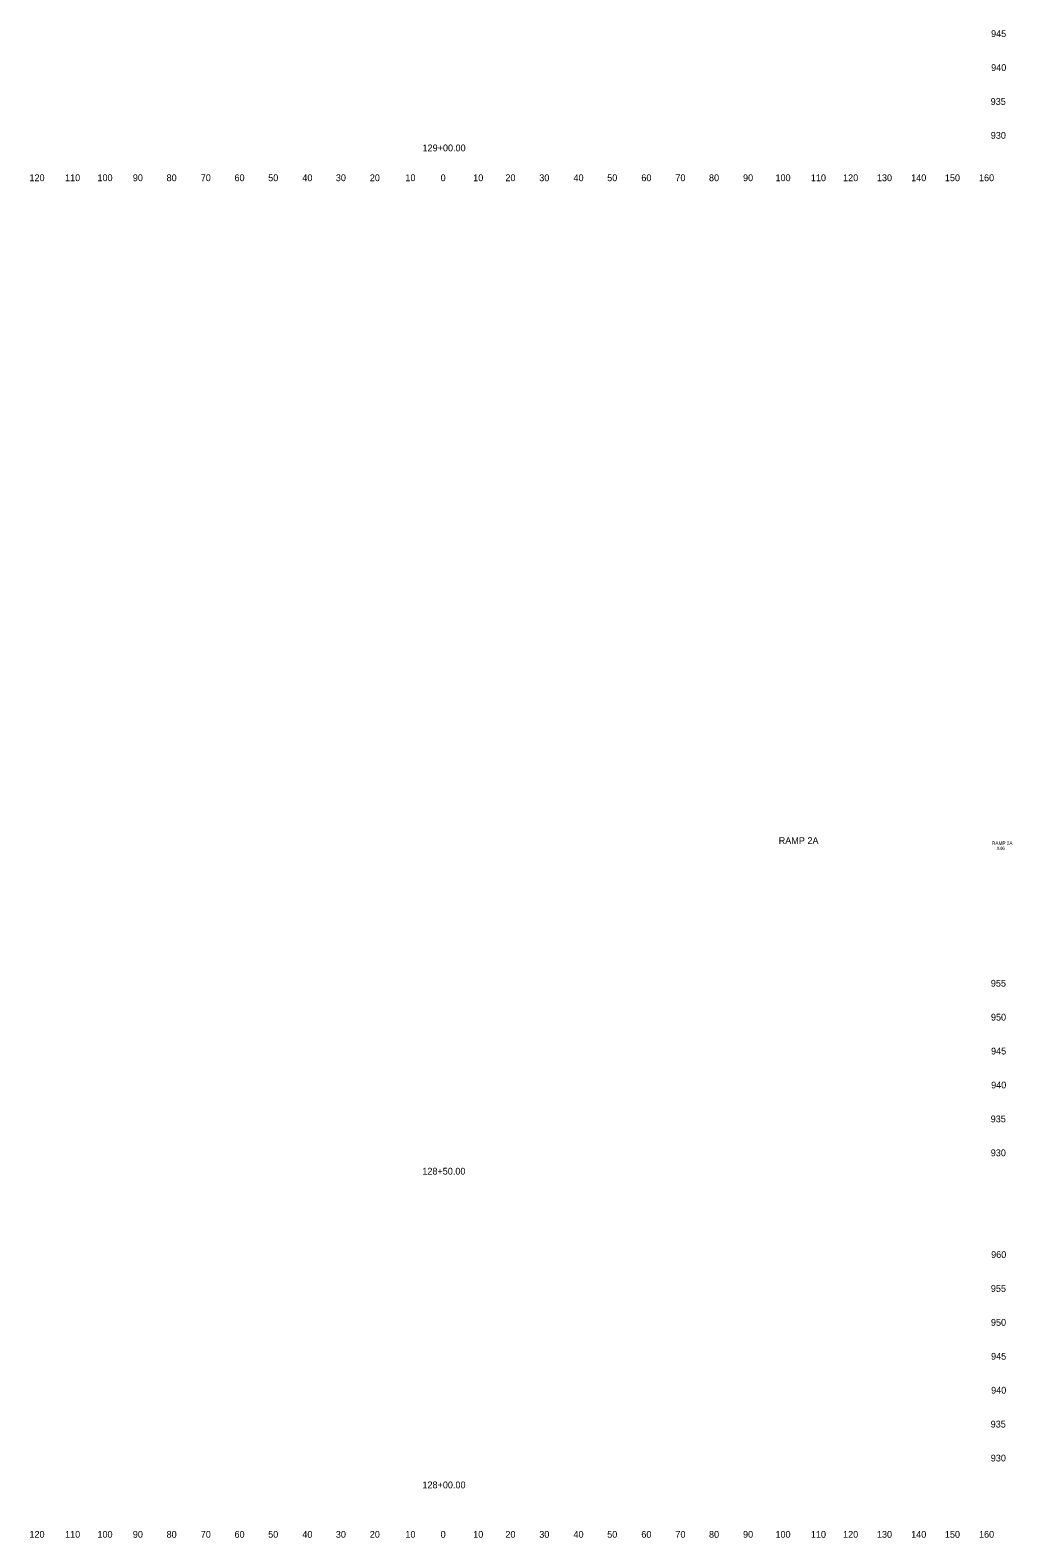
# Model space of a CAD drawing. Extents: x 4994 to 7388, y 4997 to 8804.
# Drawn here: x 7098.2 to 7387.8, y 6997.5 to 7442 of the extents above; entities that cross this region are included whole.
import ezdxf

# ---------------------------------------------------------------- set-up
doc = ezdxf.new("R2010")
doc.units = 0
for name, color, linetype in [('RD_SHT_ID', 7, 'Continuous'), ('RD_XS_TX_Offset', 7, 'Continuous'), ('RD_XS_TX_Station', 7, 'Continuous')]:
    doc.layers.add(name, color=color, linetype=linetype)

msp = doc.modelspace()

# ---------------------------------------------------------------- texts
at = {"layer": 'RD_SHT_ID'}
for s, height, p in [('RAMP 2A', 2, (7319.02, 7202.06)), ('RAMP 2A', 1, (7381.93, 7201.8)), ('X46', 1, (7383.26, 7200.3))]:
    msp.add_text(s, height=height, dxfattribs=at).set_placement(p)
at = {"layer": 'RD_XS_TX_Offset'}
for s, p in [('945', (7381.66, 7440)), ('940', (7381.69, 7430)), ('935', (7381.55, 7420)), ('930', (7381.58, 7410)), ('120', (7098.01, 7397.5)), ('110', (7108.51, 7397.5)), ('100', (7118.07, 7397.5)), ('90', (7128.5, 7397.5)), ('80', (7138.46, 7397.5)), ('70', (7148.54, 7397.5)), ('60', (7158.5, 7397.5)), ('50', (7168.43, 7397.5)), ('40', (7178.5, 7397.5)), ('30', (7188.39, 7397.5)), ('20', (7198.4, 7397.5)), ('10', (7208.91, 7397.5)), ('0', (7219.3, 7397.5)), ('0', (7219.3, 7397.5)), ('10', (7228.91, 7397.5)), ('20', (7238.4, 7397.5)), ('30', (7248.39, 7397.5)), ('40', (7258.5, 7397.5)), ('50', (7268.43, 7397.5)), ('60', (7278.5, 7397.5)), ('70', (7288.54, 7397.5)), ('80', (7298.46, 7397.5)), ('90', (7308.5, 7397.5)), ('100', (7318.07, 7397.5)), ('110', (7328.51, 7397.5)), ('120', (7338.01, 7397.5)), ('130', (7347.99, 7397.5)), ('140', (7358.1, 7397.5)), ('150', (7368.04, 7397.5)), ('160', (7378.1, 7397.5)), ('955', (7381.6, 7160)), ('950', (7381.63, 7150)), ('945', (7381.66, 7140)), ('940', (7381.69, 7130)), ('935', (7381.55, 7120)), ('930', (7381.58, 7110)), ('960', (7381.69, 7080)), ('955', (7381.6, 7070)), ('950', (7381.63, 7060)), ('945', (7381.66, 7050)), ('940', (7381.69, 7040)), ('935', (7381.55, 7030)), ('930', (7381.58, 7020)), ('120', (7098.01, 6997.5)), ('110', (7108.51, 6997.5)), ('100', (7118.07, 6997.5)), ('90', (7128.5, 6997.5)), ('80', (7138.46, 6997.5)), ('70', (7148.54, 6997.5)), ('60', (7158.5, 6997.5)), ('50', (7168.43, 6997.5)), ('40', (7178.5, 6997.5)), ('30', (7188.39, 6997.5)), ('20', (7198.4, 6997.5)), ('10', (7208.91, 6997.5)), ('0', (7219.3, 6997.5)), ('0', (7219.3, 6997.5)), ('10', (7228.91, 6997.5)), ('20', (7238.4, 6997.5)), ('30', (7248.39, 6997.5)), ('40', (7258.5, 6997.5)), ('50', (7268.43, 6997.5)), ('60', (7278.5, 6997.5)), ('70', (7288.54, 6997.5)), ('80', (7298.46, 6997.5)), ('90', (7308.5, 6997.5)), ('100', (7318.07, 6997.5)), ('110', (7328.51, 6997.5)), ('120', (7338.01, 6997.5)), ('130', (7347.99, 6997.5)), ('140', (7358.1, 6997.5)), ('150', (7368.04, 6997.5)), ('160', (7378.1, 6997.5))]:
    msp.add_text(s, height=2, dxfattribs=at).set_placement(p)
at = {"layer": 'RD_XS_TX_Station'}
for s, p in [('129+00.00', (7213.96, 7406.31)), ('128+50.00', (7213.9, 7104.58)), ('128+00.00', (7213.93, 7012.08))]:
    msp.add_text(s, height=2, dxfattribs=at).set_placement(p)

doc.saveas('drawing.dxf')
